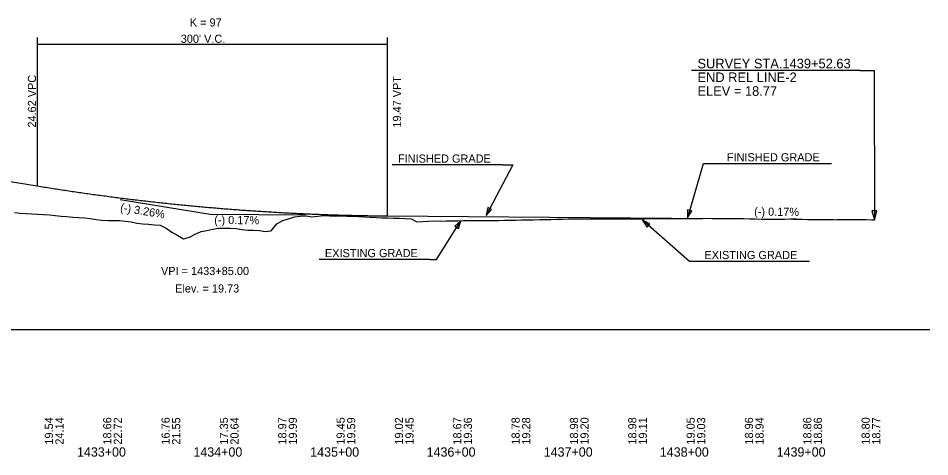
# Model space of a CAD drawing. Extents: x 2360994 to 2383826, y 330623 to 403123.
# Drawn here: x 2369844 to 2370626, y 381764 to 382140 of the extents above; entities that cross this region are included whole.
import ezdxf

# ---------------------------------------------------------------- set-up
doc = ezdxf.new("R2010")
doc.units = 0
for name, color, linetype in [('RD_DDB_GradeTX', 7, 'Continuous'), ('RD_DDB_Profile_EX', 7, 'Continuous'), ('RD_DDB_Profile_Lbl', 7, 'Continuous'), ('RD_DDB_Profile_PR', 7, 'Continuous'), ('RD_DDB_StaTX', 7, 'Continuous'), ('RD_DDB_StripGrade', 7, 'Continuous'), ('RD_DDB_VCLbl', 7, 'Continuous'), ('RD_GPK_Profile_Cell', 7, 'Continuous'), ('RD_TX_Profile', 7, 'Continuous')]:
    doc.layers.add(name, color=color, linetype=linetype)

msp = doc.modelspace()

# ---------------------------------------------------------------- linework, layer by layer
at = {"layer": 'RD_DDB_GradeTX'}
for p in [(2369931.61, 381984.39), (2370090.56, 381970.83)]:
    msp.add_line(p, (2370010.57, 381971.51), dxfattribs=at)
at = {"layer": 'RD_DDB_Profile_EX'}
for points in [[(2369840.97, 381973.05), (2369845.97, 381972.62), (2369850.97, 381972.3), (2369855.97, 381971.99), (2369860.97, 381971.67), (2369865.97, 381971.36)], [(2369865.97, 381971.36), (2369870.97, 381971.03), (2369875.97, 381970.57), (2369880.97, 381970.1), (2369885.97, 381969.63), (2369890.97, 381969.13), (2369895.97, 381968.79), (2369900.97, 381968.7), (2369905.97, 381968.03), (2369910.97, 381967.15), (2369915.97, 381966.54), (2369920.97, 381966.32), (2369925.97, 381966.16), (2369930.97, 381966.21), (2369935.97, 381965.83), (2369940.97, 381965.06), (2369945.97, 381964), (2369950.97, 381963.49), (2369955.97, 381963.05), (2369960.97, 381962.62), (2369965.97, 381962.17), (2369970.97, 381959.7), (2369975.97, 381956.41), (2369980.97, 381953.45), (2369985.97, 381950.7), (2369990.97, 381952.11), (2369995.97, 381954.63), (2370000.97, 381956.77), (2370005.97, 381957.83), (2370010.97, 381958.95), (2370015.97, 381959.66), (2370020.97, 381959.62), (2370025.97, 381959.61), (2370030.97, 381959.44), (2370035.97, 381958.67), (2370040.97, 381958.03), (2370045.97, 381958.1), (2370050.97, 381957.74), (2370055.97, 381956.96), (2370060.97, 381957.36), (2370065.97, 381963.4), (2370070.97, 381966.29), (2370075.97, 381967.85), (2370080.97, 381969.42), (2370085.97, 381970.12), (2370090.97, 381970.2), (2370095.97, 381969.3), (2370100.97, 381969.88), (2370105.97, 381970.55), (2370110.97, 381970.17), (2370115.97, 381969.96), (2370120.97, 381970.18), (2370125.97, 381970.12), (2370130.97, 381969.93), (2370135.97, 381969.82), (2370140.97, 381969.42), (2370145.97, 381969.19), (2370150.97, 381968.87), (2370155.97, 381968.6), (2370160.97, 381968.52), (2370165.97, 381968.31), (2370170.97, 381968.26), (2370175.97, 381967.97), (2370180.97, 381967.72), (2370185.97, 381965.22), (2370190.97, 381965.53), (2370195.97, 381965.75), (2370200.97, 381965.92), (2370205.97, 381965.85), (2370210.97, 381965.9), (2370215.97, 381966.02), (2370220.97, 381966.14), (2370225.97, 381966.25), (2370230.97, 381966.37), (2370235.97, 381966.4), (2370240.97, 381966.4), (2370245.97, 381966.4), (2370250.97, 381966.39), (2370255.97, 381966.39), (2370260.97, 381966.51), (2370265.97, 381966.62), (2370270.97, 381966.72), (2370275.97, 381966.81), (2370280.97, 381966.9), (2370285.97, 381966.94), (2370290.97, 381967.03), (2370295.97, 381967.13), (2370300.97, 381967.22), (2370305.97, 381967.31), (2370310.97, 381967.53), (2370315.97, 381967.64), (2370320.97, 381967.73), (2370325.97, 381967.79), (2370330.97, 381967.7), (2370335.97, 381967.67), (2370340.97, 381967.67), (2370345.97, 381967.68), (2370350.97, 381967.68), (2370355.97, 381967.68), (2370360.97, 381967.68), (2370365.97, 381967.73)], [(2370365.97, 381967.73), (2370370.97, 381967.76), (2370375.97, 381967.81), (2370380.97, 381967.85), (2370385.97, 381967.89), (2370390.97, 381967.88), (2370395.97, 381967.87), (2370400.97, 381967.86), (2370405.97, 381967.87), (2370410.97, 381967.91), (2370415.97, 381968.05), (2370420.97, 381968.11), (2370425.97, 381968.14), (2370430.97, 381968.15), (2370435.97, 381968.16), (2370440.97, 381968.15), (2370445.97, 381968.14), (2370450.97, 381968.13), (2370455.97, 381968.07), (2370460.97, 381967.98), (2370465.97, 381967.87), (2370470.97, 381967.76), (2370475.97, 381967.66), (2370480.97, 381967.51), (2370485.97, 381967.45), (2370490.97, 381967.47), (2370495.97, 381967.46), (2370500.97, 381967.45), (2370505.97, 381967.59), (2370510.97, 381967.63), (2370515.97, 381967.45), (2370520.97, 381967.25), (2370525.97, 381967.15), (2370530.97, 381967.08), (2370535.97, 381967.03), (2370540.97, 381967.01), (2370545.97, 381967.02), (2370550.97, 381967.05), (2370555.97, 381967.1), (2370560.97, 381967.16), (2370565.97, 381967.09), (2370570.97, 381967.02), (2370575.97, 381966.88), (2370578.2, 381966.83)]]:
    msp.add_lwpolyline(points, dxfattribs=at)
at = {"layer": 'RD_DDB_Profile_PR'}
for p, q in [((2369810.57, 382004.13), (2369860.57, 381995.98)), ((2370160.57, 381970.24), (2370578.2, 381966.73))]:
    msp.add_line(p, q, dxfattribs=at)
msp.add_spline([(2369860.57, 381995.98), (2369866.57, 381995.01), (2369872.57, 381994.06), (2369878.57, 381993.12), (2369884.57, 381992.21), (2369890.57, 381991.31), (2369896.57, 381990.44), (2369902.57, 381989.58), (2369908.57, 381988.74), (2369914.57, 381987.92), (2369920.57, 381987.12), (2369926.57, 381986.33), (2369932.57, 381985.57), (2369938.57, 381984.82), (2369944.57, 381984.09), (2369950.57, 381983.38), (2369956.57, 381982.69), (2369962.57, 381982.02), (2369968.57, 381981.37), (2369974.57, 381980.73), (2369980.57, 381980.11), (2369986.57, 381979.52), (2369992.57, 381978.94), (2369998.57, 381978.37), (2370004.57, 381977.83), (2370010.57, 381977.31), (2370016.57, 381976.8), (2370022.57, 381976.32), (2370028.57, 381975.85), (2370034.57, 381975.4), (2370040.57, 381974.97), (2370046.57, 381974.55), (2370052.57, 381974.16), (2370058.57, 381973.79), (2370064.57, 381973.43), (2370070.57, 381973.09), (2370076.57, 381972.77), (2370082.57, 381972.47), (2370088.57, 381972.19), (2370094.57, 381971.92), (2370100.57, 381971.68), (2370106.57, 381971.45), (2370112.57, 381971.24), (2370118.57, 381971.05), (2370124.57, 381970.88), (2370130.57, 381970.73), (2370136.57, 381970.59), (2370142.57, 381970.48), (2370148.57, 381970.38), (2370154.57, 381970.3), (2370160.57, 381970.24)], degree=3, dxfattribs=at)
at = {"layer": 'RD_DDB_VCLbl'}
for p, q in [((2369860.57, 382123.22), (2369860.57, 381995.98)), ((2370160.57, 382123.22), (2370160.57, 381970.24)), ((2369860.57, 382117.47), (2370160.57, 382117.47))]:
    msp.add_line(p, q, dxfattribs=at)
at = {"layer": 'RD_GPK_Profile_Cell'}
msp.add_line((2368825.57, 381872.88), (2370625.57, 381872.88), dxfattribs=at)
at = {"layer": 'RD_TX_Profile'}
for p, q in [((2370566.02, 382095.06), (2370421.47, 382095.06)), ((2370259.34, 382013.92), (2370164.78, 382013.92)), ((2370541.24, 382015.04), (2370446.67, 382015.04)), ((2370197.31, 381932.86), (2370102.18, 381932.86)), ((2370522.57, 381931.19), (2370427.44, 381931.19))]:
    msp.add_line(p, q, dxfattribs=at)
for points in [[(2370566.02, 382095.06), (2370577.98, 382095.06), (2370578.2, 381966.73)], [(2370259.34, 382013.92), (2370268.14, 382013.92), (2370245.29, 381970.68)], [(2370446.67, 382015.04), (2370431.23, 382015.04), (2370417.94, 381968.48)], [(2370197.31, 381932.86), (2370202.92, 381932.86), (2370223.69, 381966.11)], [(2370427.44, 381931.19), (2370419.76, 381931.19), (2370379.47, 381966.53)]]:
    msp.add_lwpolyline(points, dxfattribs=at)
for points in [[(2370246.85, 381977.51), (2370245.29, 381970.68), (2370250.05, 381975.82)], [(2370418.05, 381975.48), (2370417.94, 381968.48), (2370421.53, 381974.49)], [(2370576.05, 381974.68), (2370578.2, 381966.73), (2370580.31, 381974.69)], [(2370221.64, 381959.42), (2370223.69, 381966.11), (2370218.57, 381961.34)], [(2370385.74, 381963.43), (2370379.47, 381966.53), (2370383.35, 381960.71)]]:
    msp.add_lwpolyline(points, close=True, dxfattribs=at)

# ---------------------------------------------------------------- texts
at = {"layer": 'RD_DDB_GradeTX'}
for s, rotation, p in [('(-) 3.26%', 350.73481, (2369931.35, 381974.23)), ('(-) 0.17%', 359.51803, (2370475.02, 381970.47)), ('(-) 0.17%', 359.51803, (2370012.27, 381963.33))]:
    msp.add_text(s, height=7, rotation=rotation, dxfattribs=at).set_placement(p)
at = {"layer": 'RD_DDB_Profile_Lbl'}
for s, p in [('VPI = 1433+85.00', (2369966.65, 381919.51)), ('Elev. = 19.73', (2369978.82, 381904.51))]:
    msp.add_text(s, height=7, dxfattribs=at).set_placement(p)
at = {"layer": 'RD_DDB_StaTX'}
for s, p in [('1433+00', (2369894.66, 381763.71)), ('1434+00', (2369994.42, 381763.71)), ('1435+00', (2370094.55, 381763.71)), ('1436+00', (2370194.32, 381763.71)), ('1437+00', (2370294.68, 381763.71)), ('1438+00', (2370394.21, 381763.71)), ('1439+00', (2370494.32, 381763.71))]:
    msp.add_text(s, height=8, dxfattribs=at).set_placement(p)
at = {"layer": 'RD_DDB_StripGrade'}
for s, p in [('24.62 VPC', (2369859.57, 382045.98)), ('19.47 VPT', (2370172.43, 382045.98)), ('19.54', (2369874.11, 381774.06)), ('24.14', (2369883.16, 381774)), ('18.66', (2369924.11, 381774.06)), ('22.72', (2369933.16, 381774)), ('16.76', (2369974.11, 381774.06)), ('21.55', (2369983.16, 381774)), ('17.35', (2370024.11, 381774.06)), ('20.64', (2370033.16, 381774)), ('18.97', (2370074.11, 381774.06)), ('19.99', (2370083.16, 381774)), ('19.45', (2370124.11, 381774.06)), ('19.59', (2370133.16, 381774)), ('19.02', (2370174.11, 381774.06)), ('19.45', (2370183.16, 381774)), ('18.67', (2370224.11, 381774.06)), ('19.36', (2370233.16, 381774)), ('18.78', (2370274.11, 381774.06)), ('19.28', (2370283.16, 381774)), ('18.98', (2370324.11, 381774.06)), ('19.20', (2370333.16, 381774)), ('18.98', (2370374.11, 381774.06)), ('19.11', (2370383.16, 381774)), ('19.05', (2370424.11, 381774.06)), ('19.03', (2370433.16, 381774)), ('18.96', (2370474.11, 381774.06)), ('18.94', (2370483.16, 381774)), ('18.86', (2370524.11, 381774.06)), ('18.86', (2370533.16, 381774)), ('18.80', (2370574.11, 381774.06)), ('18.77', (2370583.16, 381774))]:
    msp.add_text(s, height=7, rotation=90, dxfattribs=at).set_placement(p)
at = {"layer": 'RD_DDB_VCLbl'}
for s, p in [('K = 97', (2369991.37, 382132.72)), ("300' V.C.", (2369983.6, 382118.72))]:
    msp.add_text(s, height=7, dxfattribs=at).set_placement(p)
at = {"layer": 'RD_TX_Profile'}
for s, height, p in [('SURVEY STA.1439+52.63', 8.2353, (2370426.47, 382096.82)), ('END REL LINE-2', 8.2353, (2370426.47, 382085.06)), ('ELEV = 18.77', 8.2353, (2370426.47, 382073.29)), ('FINISHED GRADE', 7, (2370169.78, 382015.92)), ('FINISHED GRADE', 7, (2370451.67, 382017.04)), ('EXISTING GRADE', 7, (2370107.18, 381934.86)), ('EXISTING GRADE', 7, (2370432.44, 381933.19))]:
    msp.add_text(s, height=height, dxfattribs=at).set_placement(p)

doc.saveas('drawing.dxf')
